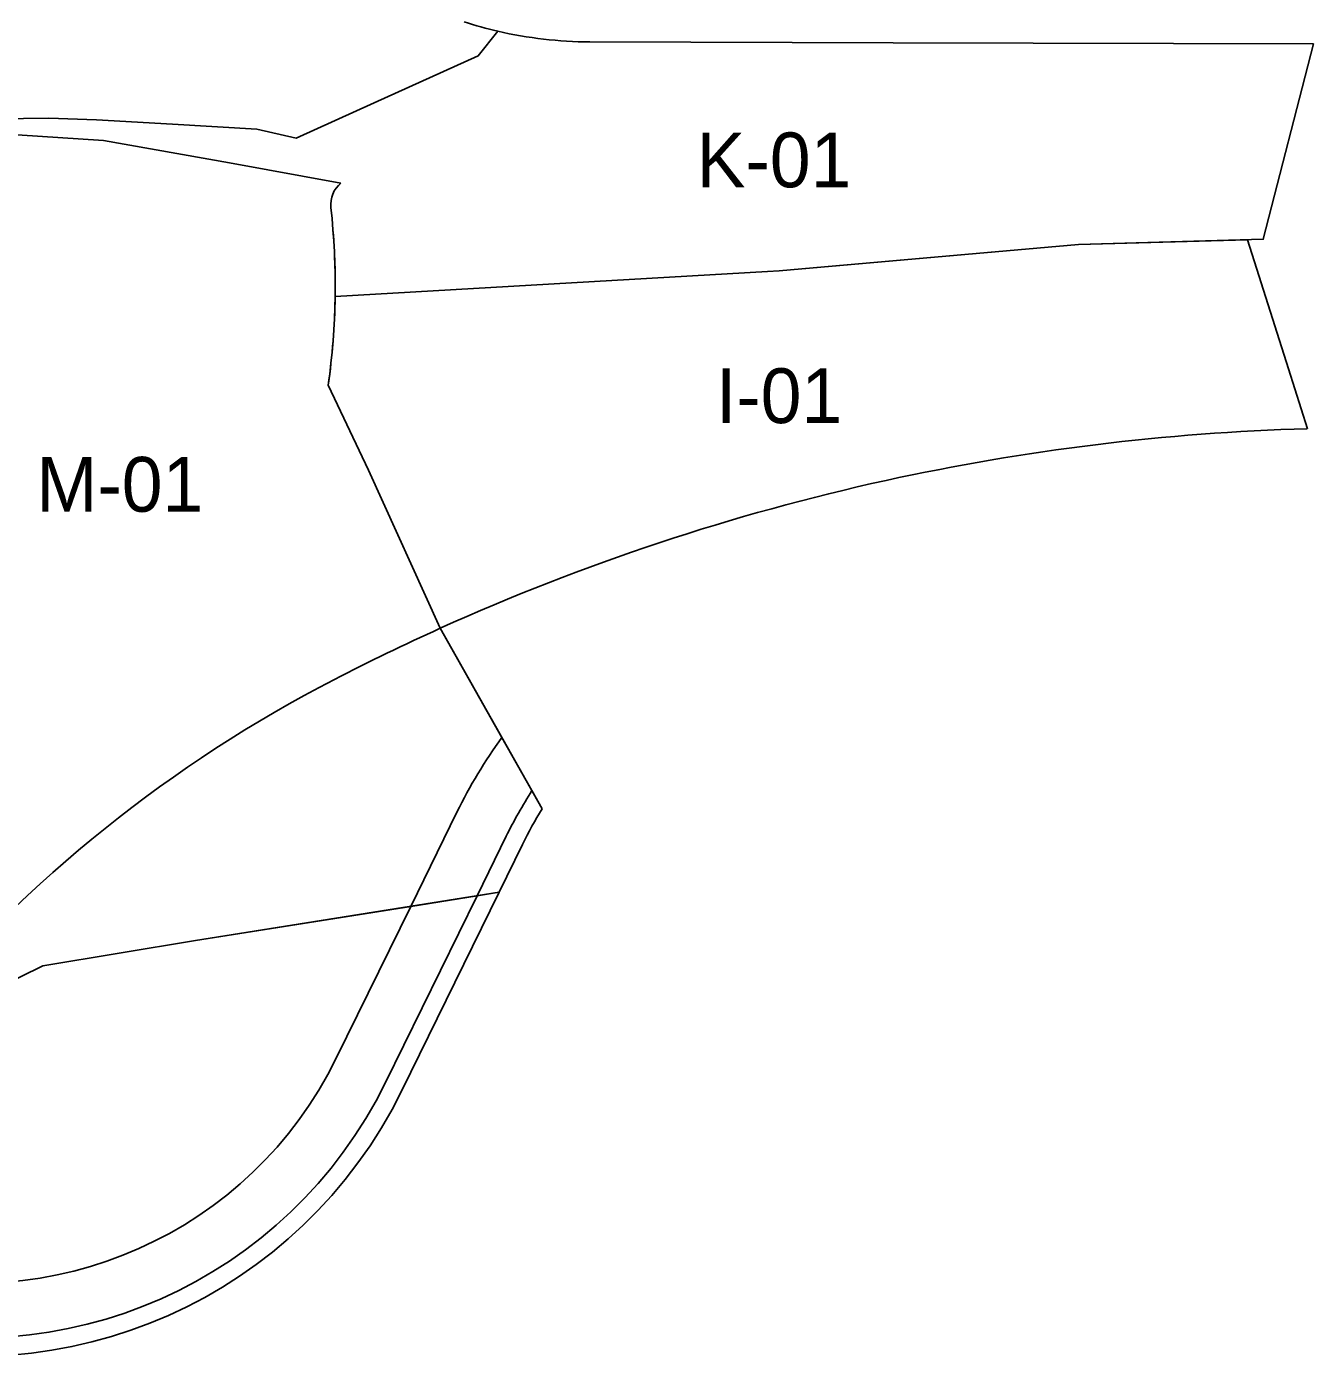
# Model space of a CAD drawing. Extents: x 5196716 to 5200291, y 3709146 to 3713154.
# Drawn here: x 5197495 to 5197635.9, y 3709226.5 to 3709372.1 of the extents above; entities that cross this region are included whole.
import ezdxf

# ---------------------------------------------------------------- set-up
doc = ezdxf.new("R2010")
doc.units = 0
for name, color, linetype in [('dsnTextNote', 7, 'Continuous'), ('Level 1', 7, 'Continuous'), ('Level 2', 7, 'Continuous'), ('Level 4', 7, 'Continuous')]:
    doc.layers.add(name, color=color, linetype=linetype)

msp = doc.modelspace()

# ---------------------------------------------------------------- linework, layer by layer
at = {"layer": 'Level 1'}
for p, q in [((5197546.63, 3709371.56), (5197544.47, 3709368.89)), ((5197589.89, 3709370.3), (5197556.68, 3709370.4)), ((5197544.47, 3709368.89), (5197533.08, 3709363.72)), ((5197533.08, 3709363.72), (5197524.56, 3709359.85)), ((5197511.01, 3709361.39), (5197502.7, 3709361.87)), ((5197489.82, 3709360.49), (5197503.44, 3709359.62)), ((5197503.44, 3709359.62), (5197489.82, 3709360.49)), ((5197489.82, 3709360.49), (5197503.44, 3709359.62)), ((5197503.44, 3709359.62), (5197517.25, 3709357.16)), ((5197517.25, 3709357.16), (5197503.44, 3709359.62)), ((5197503.44, 3709359.62), (5197517.25, 3709357.16)), ((5197517.25, 3709357.16), (5197529.45, 3709354.94)), ((5197529.45, 3709354.94), (5197517.25, 3709357.16)), ((5197517.25, 3709357.16), (5197529.45, 3709354.94)), ((5197628.68, 3709348.75), (5197610.18, 3709348.24)), ((5197610.18, 3709348.24), (5197577.4, 3709345.34)), ((5197577.4, 3709345.34), (5197583.62, 3709345.89)), ((5197576.15, 3709345.26), (5197528.81, 3709342.53)), ((5197528.81, 3709342.53), (5197576.15, 3709345.26)), ((5197577.4, 3709345.34), (5197576.15, 3709345.26)), ((5197576.15, 3709345.26), (5197577.4, 3709345.34)), ((5197528.05, 3709332.81), (5197532.48, 3709323.52)), ((5197532.48, 3709323.52), (5197528.05, 3709332.81)), ((5197532.48, 3709323.52), (5197540.3, 3709306.21)), ((5197540.3, 3709306.21), (5197532.48, 3709323.52)), ((5197551.48, 3709286.46), (5197540.3, 3709306.21)), ((5197546.76, 3709277.31), (5197549.33, 3709282.56)), ((5197546.76, 3709277.31), (5197536.12, 3709255.62)), ((5197544.34, 3709276.92), (5197546.76, 3709277.31)), ((5197513.52, 3709272.03), (5197537.1, 3709275.77)), ((5197537.1, 3709275.77), (5197544.34, 3709276.92)), ((5197496.83, 3709269.25), (5197513.52, 3709272.03)), ((5197484.92, 3709263.43), (5197496.83, 3709269.25))]:
    msp.add_line(p, q, dxfattribs=at)
for points in [[(5197524.56, 3709359.85), (5197533.08, 3709363.72), (5197544.47, 3709368.89), (5197546.63, 3709371.56)], [(5197583.62, 3709345.89), (5197610.18, 3709348.24), (5197630.4, 3709348.8), (5197635.89, 3709370.17), (5197589.89, 3709370.3)], [(5197502.7, 3709361.87), (5197497.48, 3709362.04), (5197489.15, 3709361.95)], [(5197489.15, 3709361.95), (5197497.48, 3709362.04), (5197502.7, 3709361.87)], [(5197502.7, 3709361.87), (5197511.01, 3709361.39), (5197520.24, 3709360.83), (5197524.56, 3709359.85)], [(5197524.56, 3709359.85), (5197520.24, 3709360.83), (5197511.01, 3709361.39)], [(5197635.23, 3709328.05), (5197633.16, 3709334.62), (5197628.68, 3709348.75)], [(5197482.26, 3709263.34), (5197484.92, 3709263.43), (5197496.83, 3709269.25), (5197513.52, 3709272.03), (5197546.76, 3709277.31)]]:
    msp.add_lwpolyline(points, dxfattribs=at)
for centre, radius, start, end in [((5197556.81, 3709415.4), 45, 252.0632, 256.9145), ((5197556.81, 3709415.4), 45, 256.9145, 269.8345), ((5197531.33, 3709352.6), 3, 128.8124, 186.35), ((5197531.33, 3709352.6), 3, 128.8124, 186.35), ((5197451.32, 3709343.7), 77.5, 351.9255, 6.35), ((5197451.32, 3709343.7), 77.5, 359.1378, 6.35), ((5197451.32, 3709343.7), 77.5, 351.9255, 359.1378), ((5197642.18, 3709080.65), 247.5, 91.6103, 102.3819), ((5197642.18, 3709080.65), 247.5, 102.3819, 114.3085), ((5197592.43, 3709261.43), 48, 148.5627, 153.8823), ((5197489.43, 3709278.51), 52, 254.0813, 333.8823)]:
    msp.add_arc(centre, radius, start, end, dxfattribs=at)
at = {"layer": 'Level 2'}
for p, q in [((5197546.63, 3709371.56), (5197544.47, 3709368.89)), ((5197589.89, 3709370.3), (5197556.68, 3709370.4)), ((5197544.47, 3709368.89), (5197533.08, 3709363.72)), ((5197533.08, 3709363.72), (5197524.56, 3709359.85)), ((5197511.01, 3709361.39), (5197502.7, 3709361.87)), ((5197503.44, 3709359.62), (5197489.82, 3709360.49)), ((5197489.82, 3709360.49), (5197503.44, 3709359.62)), ((5197517.25, 3709357.16), (5197503.44, 3709359.62)), ((5197503.44, 3709359.62), (5197517.25, 3709357.16)), ((5197529.45, 3709354.94), (5197517.25, 3709357.16)), ((5197517.25, 3709357.16), (5197529.45, 3709354.94)), ((5197628.68, 3709348.75), (5197610.18, 3709348.24)), ((5197610.18, 3709348.24), (5197583.62, 3709345.89)), ((5197577.4, 3709345.34), (5197583.62, 3709345.89)), ((5197583.62, 3709345.89), (5197577.4, 3709345.34)), ((5197528.81, 3709342.53), (5197576.15, 3709345.26)), ((5197576.15, 3709345.26), (5197528.81, 3709342.53)), ((5197576.15, 3709345.26), (5197577.4, 3709345.34)), ((5197577.4, 3709345.34), (5197576.15, 3709345.26)), ((5197532.48, 3709323.52), (5197528.05, 3709332.81)), ((5197528.05, 3709332.81), (5197532.48, 3709323.52)), ((5197540.3, 3709306.21), (5197532.48, 3709323.52)), ((5197532.48, 3709323.52), (5197540.3, 3709306.21)), ((5197550.36, 3709288.44), (5197547.06, 3709294.26)), ((5197542.15, 3709286.08), (5197537.1, 3709275.77)), ((5197544.34, 3709276.92), (5197547.54, 3709283.44)), ((5197537.1, 3709275.77), (5197528.94, 3709259.14)), ((5197534.33, 3709256.5), (5197544.34, 3709276.92)), ((5197537.1, 3709275.77), (5197544.34, 3709276.92)), ((5197544.34, 3709276.92), (5197537.1, 3709275.77))]:
    msp.add_line(p, q, dxfattribs=at)
for points in [[(5197524.56, 3709359.85), (5197533.08, 3709363.72), (5197544.47, 3709368.89), (5197546.63, 3709371.56)], [(5197583.62, 3709345.89), (5197610.18, 3709348.24), (5197630.4, 3709348.8), (5197635.89, 3709370.17), (5197589.89, 3709370.3)], [(5197489.15, 3709361.95), (5197497.48, 3709362.04), (5197502.7, 3709361.87)], [(5197502.7, 3709361.87), (5197497.48, 3709362.04), (5197489.15, 3709361.95)], [(5197502.7, 3709361.87), (5197511.01, 3709361.39), (5197520.24, 3709360.83), (5197524.56, 3709359.85)], [(5197524.56, 3709359.85), (5197520.24, 3709360.83), (5197511.01, 3709361.39)], [(5197635.23, 3709328.05), (5197633.16, 3709334.62), (5197628.68, 3709348.75)]]:
    msp.add_lwpolyline(points, dxfattribs=at)
for centre, radius, start, end in [((5197556.81, 3709415.4), 45, 252.0632, 256.9145), ((5197556.81, 3709415.4), 45, 256.9145, 269.8345), ((5197531.33, 3709352.6), 3, 128.8124, 186.35), ((5197531.33, 3709352.6), 3, 128.8124, 186.35), ((5197451.32, 3709343.7), 77.5, 351.9255, 6.35), ((5197451.32, 3709343.7), 77.5, 359.1378, 6.35), ((5197451.32, 3709343.7), 77.5, 351.9255, 359.1378), ((5197642.18, 3709080.65), 247.5, 91.6103, 102.3819), ((5197642.18, 3709080.65), 247.5, 102.3819, 114.3085), ((5197642.18, 3709080.65), 247.5, 114.3085, 117.2834), ((5197597.49, 3709167.3), 150, 117.2834, 140.1911), ((5197592.43, 3709261.43), 56, 144.1077, 153.8823), ((5197592.43, 3709261.43), 50, 147.2973, 153.8823), ((5197489.43, 3709278.51), 44, 254.0813, 333.8823), ((5197489.43, 3709278.51), 50, 254.0813, 333.8823)]:
    msp.add_arc(centre, radius, start, end, dxfattribs=at)
at = {"layer": 'Level 4'}
for p, q in [((5197547.06, 3709294.26), (5197540.3, 3709306.21)), ((5197551.48, 3709286.46), (5197550.36, 3709288.44)), ((5197537.1, 3709275.77), (5197542.15, 3709286.08)), ((5197547.54, 3709283.44), (5197544.34, 3709276.92)), ((5197546.76, 3709277.31), (5197549.33, 3709282.56)), ((5197536.12, 3709255.62), (5197546.76, 3709277.31)), ((5197544.34, 3709276.92), (5197546.76, 3709277.31)), ((5197546.76, 3709277.31), (5197544.34, 3709276.92)), ((5197537.1, 3709275.77), (5197513.52, 3709272.03)), ((5197528.94, 3709259.14), (5197537.1, 3709275.77)), ((5197544.34, 3709276.92), (5197534.33, 3709256.5))]:
    msp.add_line(p, q, dxfattribs=at)
for points in [[(5197482.26, 3709263.34), (5197484.92, 3709263.43), (5197496.83, 3709269.25), (5197513.52, 3709272.03), (5197537.1, 3709275.77)], [(5197513.52, 3709272.03), (5197496.83, 3709269.25), (5197484.92, 3709263.43)]]:
    msp.add_lwpolyline(points, dxfattribs=at)
for centre, radius, start, end in [((5197642.18, 3709080.65), 247.5, 114.3085, 117.2834), ((5197597.49, 3709167.3), 150, 117.2834, 140.1911), ((5197592.43, 3709261.43), 56, 144.1077, 153.8823), ((5197592.43, 3709261.43), 50, 147.2973, 153.8823), ((5197592.43, 3709261.43), 48, 148.5627, 153.8823), ((5197489.43, 3709278.51), 44, 254.0813, 333.8823), ((5197489.43, 3709278.51), 52, 254.0813, 333.8823), ((5197489.43, 3709278.51), 50, 254.0813, 333.8823)]:
    msp.add_arc(centre, radius, start, end, dxfattribs=at)

# ---------------------------------------------------------------- texts
at = {"layer": 'dsnTextNote'}
for s, p in [('K-01', (5197568.37, 3709354.48)), ('I-01', (5197570.49, 3709328.67)), ('M-01', (5197496.1, 3709318.97))]:
    msp.add_text(s, height=6, dxfattribs=at).set_placement(p)

doc.saveas('drawing.dxf')
